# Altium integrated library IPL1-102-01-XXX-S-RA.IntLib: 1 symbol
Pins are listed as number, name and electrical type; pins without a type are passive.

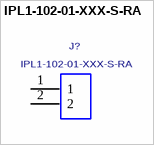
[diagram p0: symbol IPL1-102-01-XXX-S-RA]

## IPL1-102-01-XXX-S-RA
designator J?
Terminal Assembly, Single Row, Right Angle, Thru-Hole, 2 Pins.; MANUFACTURER: SAMTEC
footprint IPL1-102-01-XXX-S-RA
pins: 1, 2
